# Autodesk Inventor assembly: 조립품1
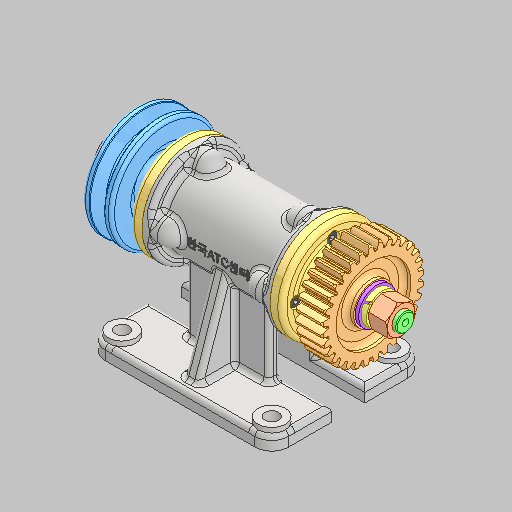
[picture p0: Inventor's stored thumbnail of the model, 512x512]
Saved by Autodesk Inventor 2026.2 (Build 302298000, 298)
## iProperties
Created: 2026-06
Part Number: 조립품1
Document SubType Name: Assembly
Designer: sec7
Author: sec7
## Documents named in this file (14)
- C:\Users\sec7\Desktop\권태윤\조립품1.iam
- C:\Users\sec7\Desktop\권태윤\본체.ipt
- C:\Users\sec7\Desktop\권태윤\부품변환\6각 너트 M12x1.ipt
- C:\Users\sec7\Desktop\권태윤\부품변환\V 벨트 풀리.ipt
- C:\Users\sec7\Desktop\권태윤\부품변환\깊은 홈 볼 베어링 6904.ipt
- C:\Users\sec7\Desktop\권태윤\부품변환\스퍼 기어.ipt
- C:\Users\sec7\Desktop\권태윤\부품변환\스프링 와셔 M12.ipt
- C:\Users\sec7\Desktop\권태윤\부품변환\오일 실 20 35 8.ipt
- C:\Users\sec7\Desktop\권태윤\부품변환\축.ipt
- C:\Users\sec7\Desktop\권태윤\부품변환\커버.ipt
- C:\Users\sec7\Desktop\권태윤\부품변환\평 와셔 M12.ipt
- C:\Users\sec7\Desktop\권태윤\부품변환\평행 키 4x4x14.ipt
- C:\Users\sec7\Desktop\권태윤\부품변환\6각 구멍붙이 볼트 M4x8.ipt
- C:\Users\sec7\Desktop\권태윤\부품변환\6각 구멍붙이 볼트 M4x8_MIR.ipt
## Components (11 placed, 4 different names)
1. 6각 너트 M12x1:1
2. V 벨트 풀리:1
3. 6각 구멍붙이 볼트 M4x8_MIR:1
4. 6각 구멍붙이 볼트 M4x8_MIR:2
5. 6각 구멍붙이 볼트 M4x8_MIR:3
6. 6각 구멍붙이 볼트 M4x8_MIR:4
7. 6각 너트 M12x1:2
8. 6각 구멍붙이 볼트 M4x8:1
9. 6각 구멍붙이 볼트 M4x8:2
10. 6각 구멍붙이 볼트 M4x8:3
11. 6각 구멍붙이 볼트 M4x8:4
